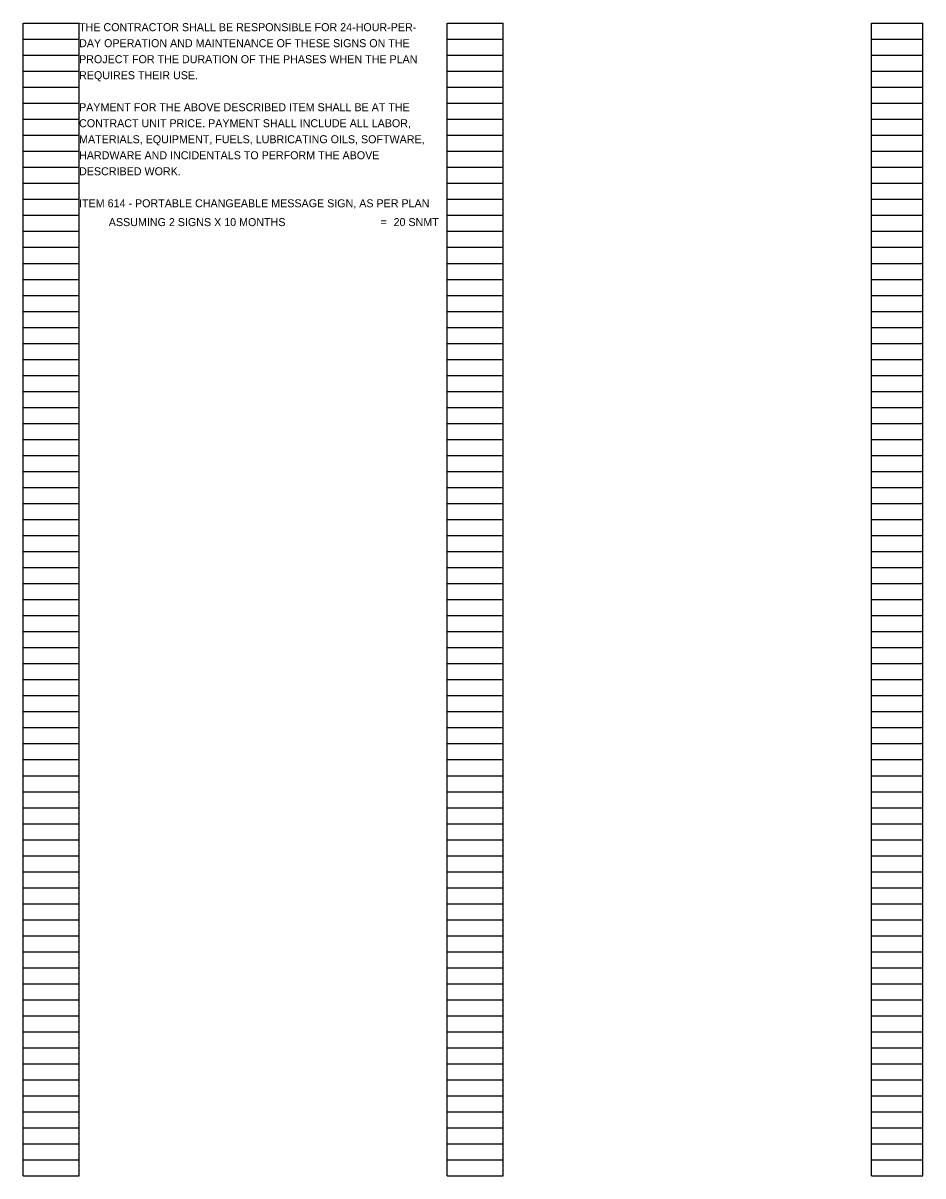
# Model space of a CAD drawing. Extents: x 0 to 32, y -44 to 21.1.
# Drawn here: x 16.26 to 32, y -21.02 to -0.86 of the extents above; entities that cross this region are included whole.
import ezdxf

# ---------------------------------------------------------------- set-up
doc = ezdxf.new("R2010")
doc.units = 0
doc.layers.add('SH_Data', color=7, linetype='Continuous')
doc.layers.add('SH_Text', color=7, linetype='Continuous')

msp = doc.modelspace()

# ---------------------------------------------------------------- linework, layer by layer
at = {"layer": 'SH_Data'}
for p, q in [((16.26, -21.02), (16.26, -0.86)), ((16.26, -0.86), (17.24, -0.86)), ((17.24, -21.02), (17.24, -0.86)), ((23.68, -21.02), (23.68, -0.86)), ((23.68, -0.86), (24.66, -0.86)), ((24.66, -21.02), (24.66, -0.86)), ((31.1, -21.02), (31.1, -0.86)), ((31.1, -0.86), (32, -0.86)), ((32, -21.02), (32, -0.86)), ((16.26, -1.14), (17.24, -1.14)), ((23.68, -1.14), (24.66, -1.14)), ((31.1, -1.14), (32, -1.14)), ((16.26, -1.42), (17.24, -1.42)), ((23.68, -1.42), (24.66, -1.42)), ((31.1, -1.42), (32, -1.42)), ((16.26, -1.7), (17.24, -1.7)), ((23.68, -1.7), (24.66, -1.7)), ((31.1, -1.7), (32, -1.7)), ((16.26, -1.98), (17.24, -1.98)), ((23.68, -1.98), (24.66, -1.98)), ((31.1, -1.98), (32, -1.98)), ((16.26, -2.26), (17.24, -2.26)), ((23.68, -2.26), (24.66, -2.26)), ((31.1, -2.26), (32, -2.26)), ((16.26, -2.54), (17.24, -2.54)), ((23.68, -2.54), (24.66, -2.54)), ((31.1, -2.54), (32, -2.54)), ((16.26, -2.82), (17.24, -2.82)), ((23.68, -2.82), (24.66, -2.82)), ((31.1, -2.82), (32, -2.82)), ((16.26, -3.1), (17.24, -3.1)), ((23.68, -3.1), (24.66, -3.1)), ((31.1, -3.1), (32, -3.1)), ((16.26, -3.38), (17.24, -3.38)), ((23.68, -3.38), (24.66, -3.38)), ((31.1, -3.38), (32, -3.38)), ((16.26, -3.66), (17.24, -3.66)), ((23.68, -3.66), (24.66, -3.66)), ((31.1, -3.66), (32, -3.66)), ((16.26, -3.94), (17.24, -3.94)), ((23.68, -3.94), (24.66, -3.94)), ((31.1, -3.94), (32, -3.94)), ((16.26, -4.22), (17.24, -4.22)), ((23.68, -4.22), (24.66, -4.22)), ((31.1, -4.22), (32, -4.22)), ((16.26, -4.5), (17.24, -4.5)), ((23.68, -4.5), (24.66, -4.5)), ((31.1, -4.5), (32, -4.5)), ((16.26, -4.78), (17.24, -4.78)), ((23.68, -4.78), (24.66, -4.78)), ((31.1, -4.78), (32, -4.78)), ((16.26, -5.06), (17.24, -5.06)), ((23.68, -5.06), (24.66, -5.06)), ((31.1, -5.06), (32, -5.06)), ((16.26, -5.34), (17.24, -5.34)), ((23.68, -5.34), (24.66, -5.34)), ((31.1, -5.34), (32, -5.34)), ((16.26, -5.62), (17.24, -5.62)), ((23.68, -5.62), (24.66, -5.62)), ((31.1, -5.62), (32, -5.62)), ((16.26, -5.9), (17.24, -5.9)), ((23.68, -5.9), (24.66, -5.9)), ((31.1, -5.9), (32, -5.9)), ((16.26, -6.18), (17.24, -6.18)), ((23.68, -6.18), (24.66, -6.18)), ((31.1, -6.18), (32, -6.18)), ((16.26, -6.46), (17.24, -6.46)), ((23.68, -6.46), (24.66, -6.46)), ((31.1, -6.46), (32, -6.46)), ((16.26, -6.74), (17.24, -6.74)), ((23.68, -6.74), (24.66, -6.74)), ((31.1, -6.74), (32, -6.74)), ((16.26, -7.02), (17.24, -7.02)), ((23.68, -7.02), (24.66, -7.02)), ((31.1, -7.02), (32, -7.02)), ((16.26, -7.3), (17.24, -7.3)), ((23.68, -7.3), (24.66, -7.3)), ((31.1, -7.3), (32, -7.3)), ((16.26, -7.58), (17.24, -7.58)), ((23.68, -7.58), (24.66, -7.58)), ((31.1, -7.58), (32, -7.58)), ((16.26, -7.86), (17.24, -7.86)), ((23.68, -7.86), (24.66, -7.86)), ((31.1, -7.86), (32, -7.86)), ((16.26, -8.14), (17.24, -8.14)), ((23.68, -8.14), (24.66, -8.14)), ((31.1, -8.14), (32, -8.14)), ((16.26, -8.42), (17.24, -8.42)), ((23.68, -8.42), (24.66, -8.42)), ((31.1, -8.42), (32, -8.42)), ((16.26, -8.7), (17.24, -8.7)), ((23.68, -8.7), (24.66, -8.7)), ((31.1, -8.7), (32, -8.7)), ((16.26, -8.98), (17.24, -8.98)), ((23.68, -8.98), (24.66, -8.98)), ((31.1, -8.98), (32, -8.98)), ((16.26, -9.26), (17.24, -9.26)), ((23.68, -9.26), (24.66, -9.26)), ((31.1, -9.26), (32, -9.26)), ((16.26, -9.54), (17.24, -9.54)), ((23.68, -9.54), (24.66, -9.54)), ((31.1, -9.54), (32, -9.54)), ((16.26, -9.82), (17.24, -9.82)), ((23.68, -9.82), (24.66, -9.82)), ((31.1, -9.82), (32, -9.82)), ((16.26, -10.1), (17.24, -10.1)), ((23.68, -10.1), (24.66, -10.1)), ((31.1, -10.1), (32, -10.1)), ((16.26, -10.38), (17.24, -10.38)), ((23.68, -10.38), (24.66, -10.38)), ((31.1, -10.38), (32, -10.38)), ((16.26, -10.66), (17.24, -10.66)), ((23.68, -10.66), (24.66, -10.66)), ((31.1, -10.66), (32, -10.66)), ((16.26, -10.94), (17.24, -10.94)), ((23.68, -10.94), (24.66, -10.94)), ((31.1, -10.94), (32, -10.94)), ((16.26, -11.22), (17.24, -11.22)), ((23.68, -11.22), (24.66, -11.22)), ((31.1, -11.22), (32, -11.22)), ((16.26, -11.5), (17.24, -11.5)), ((23.68, -11.5), (24.66, -11.5)), ((31.1, -11.5), (32, -11.5)), ((16.26, -11.78), (17.24, -11.78)), ((23.68, -11.78), (24.66, -11.78)), ((31.1, -11.78), (32, -11.78)), ((16.26, -12.06), (17.24, -12.06)), ((23.68, -12.06), (24.66, -12.06)), ((31.1, -12.06), (32, -12.06)), ((16.26, -12.34), (17.24, -12.34)), ((23.68, -12.34), (24.66, -12.34)), ((31.1, -12.34), (32, -12.34)), ((16.26, -12.62), (17.24, -12.62)), ((23.68, -12.62), (24.66, -12.62)), ((31.1, -12.62), (32, -12.62)), ((16.26, -12.9), (17.24, -12.9)), ((23.68, -12.9), (24.66, -12.9)), ((31.1, -12.9), (32, -12.9)), ((16.26, -13.18), (17.24, -13.18)), ((23.68, -13.18), (24.66, -13.18)), ((31.1, -13.18), (32, -13.18)), ((16.26, -13.46), (17.24, -13.46)), ((23.68, -13.46), (24.66, -13.46)), ((31.1, -13.46), (32, -13.46)), ((16.26, -13.74), (17.24, -13.74)), ((23.68, -13.74), (24.66, -13.74)), ((31.1, -13.74), (32, -13.74)), ((16.26, -14.02), (17.24, -14.02)), ((23.68, -14.02), (24.66, -14.02)), ((31.1, -14.02), (32, -14.02)), ((16.26, -14.3), (17.24, -14.3)), ((23.68, -14.3), (24.66, -14.3)), ((31.1, -14.3), (32, -14.3)), ((16.26, -14.58), (17.24, -14.58)), ((23.68, -14.58), (24.66, -14.58)), ((31.1, -14.58), (32, -14.58)), ((16.26, -14.86), (17.24, -14.86)), ((23.68, -14.86), (24.66, -14.86)), ((31.1, -14.86), (32, -14.86)), ((16.26, -15.14), (17.24, -15.14)), ((23.68, -15.14), (24.66, -15.14)), ((31.1, -15.14), (32, -15.14)), ((16.26, -15.42), (17.24, -15.42)), ((23.68, -15.42), (24.66, -15.42)), ((31.1, -15.42), (32, -15.42)), ((16.26, -15.7), (17.24, -15.7)), ((23.68, -15.7), (24.66, -15.7)), ((31.1, -15.7), (32, -15.7)), ((16.26, -15.98), (17.24, -15.98)), ((23.68, -15.98), (24.66, -15.98)), ((31.1, -15.98), (32, -15.98)), ((16.26, -16.26), (17.24, -16.26)), ((23.68, -16.26), (24.66, -16.26)), ((31.1, -16.26), (32, -16.26)), ((16.26, -16.54), (17.24, -16.54)), ((23.68, -16.54), (24.66, -16.54)), ((31.1, -16.54), (32, -16.54)), ((16.26, -16.82), (17.24, -16.82)), ((23.68, -16.82), (24.66, -16.82)), ((31.1, -16.82), (32, -16.82)), ((16.26, -17.1), (17.24, -17.1)), ((23.68, -17.1), (24.66, -17.1)), ((31.1, -17.1), (32, -17.1)), ((16.26, -17.38), (17.24, -17.38)), ((23.68, -17.38), (24.66, -17.38)), ((31.1, -17.38), (32, -17.38)), ((16.26, -17.66), (17.24, -17.66)), ((23.68, -17.66), (24.66, -17.66)), ((31.1, -17.66), (32, -17.66)), ((16.26, -17.94), (17.24, -17.94)), ((23.68, -17.94), (24.66, -17.94)), ((31.1, -17.94), (32, -17.94)), ((16.26, -18.22), (17.24, -18.22)), ((23.68, -18.22), (24.66, -18.22)), ((31.1, -18.22), (32, -18.22)), ((16.26, -18.5), (17.24, -18.5)), ((23.68, -18.5), (24.66, -18.5)), ((31.1, -18.5), (32, -18.5)), ((16.26, -18.78), (17.24, -18.78)), ((23.68, -18.78), (24.66, -18.78)), ((31.1, -18.78), (32, -18.78)), ((16.26, -19.06), (17.24, -19.06)), ((23.68, -19.06), (24.66, -19.06)), ((31.1, -19.06), (32, -19.06)), ((16.26, -19.34), (17.24, -19.34)), ((23.68, -19.34), (24.66, -19.34)), ((31.1, -19.34), (32, -19.34)), ((16.26, -19.62), (17.24, -19.62)), ((23.68, -19.62), (24.66, -19.62)), ((31.1, -19.62), (32, -19.62)), ((16.26, -19.9), (17.24, -19.9)), ((23.68, -19.9), (24.66, -19.9)), ((31.1, -19.9), (32, -19.9)), ((16.26, -20.18), (17.24, -20.18)), ((23.68, -20.18), (24.66, -20.18)), ((31.1, -20.18), (32, -20.18)), ((16.26, -20.46), (17.24, -20.46)), ((23.68, -20.46), (24.66, -20.46)), ((31.1, -20.46), (32, -20.46)), ((16.26, -20.74), (17.24, -20.74)), ((23.68, -20.74), (24.66, -20.74)), ((31.1, -20.74), (32, -20.74)), ((16.26, -21.02), (17.24, -21.02)), ((23.68, -21.02), (24.66, -21.02)), ((31.1, -21.02), (32, -21.02))]:
    msp.add_line(p, q, dxfattribs=at)

# ---------------------------------------------------------------- texts
at = {"layer": 'SH_Text'}
for s, p in [('THE CONTRACTOR SHALL BE RESPONSIBLE FOR 24-HOUR-PER-', (17.24, -1)), ('DAY OPERATION AND MAINTENANCE OF THESE SIGNS ON THE', (17.24, -1.28)), ('PROJECT FOR THE DURATION OF THE PHASES WHEN THE PLAN', (17.24, -1.56)), ('REQUIRES THEIR USE.', (17.24, -1.84)), ('PAYMENT FOR THE ABOVE DESCRIBED ITEM SHALL BE AT THE', (17.24, -2.4)), ('CONTRACT UNIT PRICE. PAYMENT SHALL INCLUDE ALL LABOR,', (17.24, -2.68)), ('MATERIALS, EQUIPMENT, FUELS, LUBRICATING OILS, SOFTWARE,', (17.24, -2.96)), ('HARDWARE AND INCIDENTALS TO PERFORM THE ABOVE', (17.24, -3.24)), ('DESCRIBED WORK.', (17.24, -3.52)), ('ITEM 614 - PORTABLE CHANGEABLE MESSAGE SIGN, AS PER PLAN', (17.24, -4.08)), ('          ASSUMING 2 SIGNS X 10 MONTHS', (17.24, -4.409)), ('=', (22.512, -4.409)), ('20 SNMT', (22.741, -4.409))]:
    msp.add_text(s, height=0.14, dxfattribs=at).set_placement(p)

doc.saveas('drawing.dxf')
